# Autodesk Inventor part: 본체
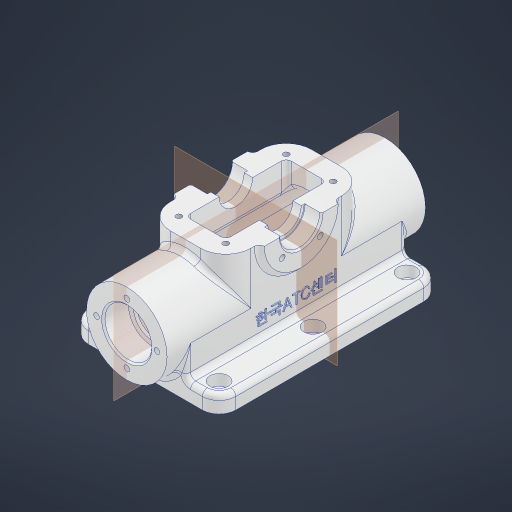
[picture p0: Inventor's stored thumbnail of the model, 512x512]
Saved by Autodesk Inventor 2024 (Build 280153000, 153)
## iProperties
Created: 2024-06
Part Number: 본체
Material: 알루미늄 6061
Document SubType Name: Modeling
Designer: kh_501
Density: 2.7 g/cm^3
Appearance: 알루미늄 - 평지
Mass: 550.949 g
Surface Area: 613.729 cm^2
Volume: 204.055 cm^3
Author: kh_501
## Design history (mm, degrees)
sketch "스케치1"
  geometry: L1 (-44, -66)-(44, -66); L2 (44, -66)-(44, 66); L3 (44, 66)-(-44, 66); L4 (-44, 66)-(-44, -66); L5 (-44, -66)-(44, 66); L6 (44, -66)-(-44, 66); 1 further point
  constraints: 12 end point, 2 midpoint, 2 parallel, 1 horizontal, 1 perpendicular
  dimensions: "d0" = 88 distance of L2.end L3.end; "d1" = 132 distance of L1.end L2.end
extrude "돌출1" new body sketch "스케치1" distance "d2" = 10; taper "d3" = 0 deg
sketch "스케치2"
  geometry: L1 (-44, 0)-(44, 0) reference; C1 r 24 at (0, 28); 2 further points
  constraints: 1 centre point, 1 midpoint, 1 vertical alignment
  dimensions: "d4" = 48 diameter of C1; "d5" = 28 distance from line of L1 C1.centre
extrude "돌출2" join sketch "스케치2" stored distance "d6" = 154; taper "d7" = 0 deg
node "작업 평면2"
sketch "스케치5"
  geometry: L1 (-44, -66)-(-15.875, -66) reference; L2 (15.875, -66)-(44, -66) reference; L3 (-44, 66)-(-44, -66) reference; L4 (-24, -77)-(24, -77) reference; L5 (24, 77)-(-24, 77) reference; L6 (15.875, -66)-(-15.875, -66) reference; L7 (15.875, 66)-(15.875, -66) reference; L8 (-15.875, 66)-(15.875, 66) reference; L9 (-15.875, -66)-(-15.875, 66) reference; L10 (24, 66)-(-24, 66); L11 (-24, 66)-(-24, -66); L12 (-24, -66)-(24, -66); L13 (24, -66)-(24, 66); L14 (24, 66)-(-24, -66); L15 (-24, 66)-(24, -66); 7 further points
  constraints: 12 end point, 2 midpoint, 2 parallel, 1 collinear, 1 horizontal, 1 perpendicular
  dimensions: "d13" = 48 distance of L11.end L12.end
extrude "돌출4" join sketch "스케치5" stored distance "d14" = 59; taper "d15" = 0 deg
sketch "스케치3"
  geometry: L1 (-24, -42)-(24, -42); L2 (24, -42)-(24, 42); L3 (24, 42)-(-24, 42); L4 (-24, 42)-(-24, -42); L5 (-24, -42)-(24, 42); L6 (24, -42)-(-24, 42); 1 further point
  constraints: 12 end point, 2 midpoint, 2 parallel, 1 horizontal, 1 perpendicular
  dimensions: "d9" = 84 distance of L1.end L2.end; "d10" = 48 distance of L2.end L3.end
extrude "돌출3" join sketch "스케치3" stored distance "d11" = 59; taper "d12" = 0 deg
sketch "스케치7"
  geometry: C1 r 24 at (0, 0) reference; 2 further points
  constraints: 1 coincident
hole "구멍1" sketch "스케치7" at (0, 0) diameter "d16" = 22; stored, may be unused: countersink angle "d20" = 90 deg, drill point angle "d22" = 118 deg; dims "d17" = 6, "d18" = 28, "d19" = 15, "d21" = 8
sketch "스케치8"
  geometry: C1 r 24 at (0, 0) reference; 2 further points
  constraints: 1 coincident
hole "구멍2" sketch "스케치8" at (0, 0) diameter "d23" = 22; stored, may be unused: countersink angle "d27" = 90 deg, drill point angle "d29" = 118 deg; dims "d24" = 6, "d25" = 28, "d26" = 15, "d28" = 8
sketch "스케치9"
  geometry: L1 (-18, 28)-(-18, 0); L2 (18, 28)-(18, 0); L3 (-24, 59)-(-24, 28) reference; L4 (-24, 10)-(-24, 28) reference; L5 (-18, 0)-(18, 0); C1 r 11 at (0, 28) reference; A1 r 18 centre (0, 28) between (-18, 28) and (18, 28); 1 further point
  constraints: 6 end point, 2 point on circle, 2 tangent, 2 vertical, 1 centre point, 1 coincident, 1 horizontal
  dimensions: "d30" = 6 distance between parallel lines of L4 L1
extrude "돌출5" cut sketch "스케치9" stored distance "d31" = 120; taper "d32" = 0 deg
sketch "스케치10"
  geometry: L1 (-24, 42)-(-24, -42) reference; L2 (-24, -42)-(24, -42) reference; L3 (24, -42)-(24, 42) reference; L4 (24, 42)-(-24, 42) reference; L5 (12, 30)-(-12, 30); L6 (-12, 30)-(-12, -30); L7 (-12, -30)-(12, -30); L8 (12, -30)-(12, 30); L9 (12, 30)-(-12, -30); L10 (-12, 30)-(12, -30); 1 further point
  constraints: 12 end point, 2 midpoint, 2 parallel, 1 horizontal, 1 perpendicular
  dimensions: "d33" = 60 distance of L5.end L6.end; "d34" = 24 distance of L5.start L5.end
extrude "돌출6" cut sketch "스케치10" stored distance "d35" = 120; taper "d36" = 0 deg
sketch "스케치11"
  geometry: L1 (24, 49)-(108, 49) reference; C1 r 22 at (66, 49); 3 further points
  constraints: 1 centre point, 1 midpoint
  dimensions: "d37" = 44 diameter of C1
extrude "돌출7" join sketch "스케치11" distance "d38" = 3; taper "d39" = 0 deg
sketch "스케치12"
  geometry: A1 r 22 centre (66, 49) between (44, 49) and (88, 49) reference; 2 further points
  constraints: 1 coincident
hole "구멍3" sketch "스케치12" at (66, 49) diameter "d40" = 20; stored, may be unused: countersink angle "d44" = 90 deg, drill point angle "d46" = 118 deg; dims "d41" = 6, "d42" = 24, "d43" = 10, "d45" = 8
sketch "스케치13"
  geometry: L1 (-17, -12)-(-27, -12) reference; L2 (-27, -12)-(-27, -22) reference; L3 (-24, -22)-(-27, -22) reference; L4 (-24, -22)-(-24, -42) reference; L5 (-24, -42)-(24, -42) reference; L6 (24, -42)-(24, -22) reference; L7 (24, -22)-(27, -22) reference; L8 (27, -12)-(27, -22) reference; L9 (27, -12)-(17, -12) reference; L10 (17, -12)-(17, -10) reference; L11 (17, -10)-(12, -10) reference; L12 (12, -10)-(12, -30) reference; L13 (12, -30)-(-12, -30) reference; L14 (-12, -30)-(-12, -10) reference; L15 (-12, -10)-(-17, -10) reference; L16 (-17, -10)-(-17, -12) reference; L17 (14, 32)-(-14, 32); L18 (-14, 32)-(-14, -32); L19 (-14, -32)-(14, -32); L20 (14, -32)-(14, 32); L21 (14, 32)-(-14, -32); L22 (-14, 32)-(14, -32); 5 further points
  constraints: 12 end point, 4 coincident, 2 midpoint, 2 parallel, 1 horizontal, 1 perpendicular
  dimensions: "d47" = 64 distance of L17.end L18.end; "d48" = 28 distance of L17.start L17.end
hole "구멍4" sketch "스케치13" at (-14, -32), (-14, 32), (14, -32), (14, 32) diameter "d49" = 3.45873; stored, may be unused: countersink angle "d53" = 90 deg, drill point angle "d55" = 118 deg; dims "d50" = 8, "d51" = 24, "d52" = 10, "d54" = 10
sketch "스케치14" dims "d56" = 36
  geometry: L1 (0, 0)-(0, 18); C1 r 24 at (0, 0) reference; 2 further points
  constraints: 2 coincident, 2 end point, 1 vertical, 1 vertical alignment, 2 other
hole "구멍5" sketch "스케치14" at (0, 18) diameter "d57" = 3.45873; stored, may be unused: countersink angle "d61" = 90 deg, drill point angle "d63" = 118 deg; dims "d58" = 8, "d59" = 4, "d60" = 2, "d62" = 10
sketch "스케치15"
  geometry: L1 (24, -66)-(44, -66) reference; L2 (-44, -66)-(-24, -66) reference; L3 (-24, -66)-(-24, 66) reference; L4 (-24, 66)-(-44, 66) reference; L5 (-44, 66)-(-44, -66) reference; L6 (-44, -66)-(-24, -66) reference; L7 (24, 66)-(24, -66) reference; L8 (24, -66)-(44, -66) reference; L9 (44, -66)-(44, 66) reference; L10 (44, 66)-(24, 66) reference; L11 (34, 56)-(-34, 56); L12 (-34, 56)-(-34, -56); L13 (-34, -56)-(34, -56); L14 (34, -56)-(34, 56); L15 (34, 56)-(-34, -56); L16 (-34, 56)-(34, -56); 7 further points
  constraints: 12 end point, 4 coincident, 4 midpoint, 2 parallel, 1 horizontal, 1 perpendicular
  dimensions: "d67" = 68 distance of L11.start L11.end; "d68" = 112 distance of L11.end L12.end
hole "구멍6" sketch "스케치15" at (34, -56), (34, 56), (-34, 56), (-34, -56), (34, 0), (-34, 0) diameter "d69" = 6.6; stored, may be unused: countersink angle "d73" = 90 deg, drill point angle "d75" = 118 deg; dims "d70" = 8, "d71" = 11, "d72" = 6.6, "d74" = 10
sketch "스케치16" dims "d76" = 32
  geometry: L1 (66, 49)-(66, 15.025); L2 (66, 49)-(35.317, 18.317); L3 (66, 49)-(96.683, 18.317); A1 r 22 centre (66, 49) between (44, 49) and (88, 49) reference; 3 further points
  constraints: 6 end point, 2 point on line, 2 symmetric about line, 1 coincident, 1 vertical, 3 other
  dimensions: "d77" = 45 deg angle of L1 L2
hole "구멍7" sketch "스케치16" at (54.686, 37.686), (77.314, 37.686) diameter "d78" = 3.45873; stored, may be unused: countersink angle "d82" = 90 deg, drill point angle "d84" = 118 deg; dims "d79" = 8, "d80" = 11, "d81" = 6.6, "d83" = 10.8
sketch "스케치17"
  geometry: L1 (0, -10)-(132, -10) reference; 3 further points
  constraints: 1 midpoint, 1 vertical alignment, 1 other
  dimensions: "d85" = 20 distance from line of L1 point (66, 10)
feature "엠보싱1" sketch "스케치17" dims "d86" = 0.5, "d87" = 0
fillet "모깎기1" dims "d88" = 15
fillet "모깎기2" dims "d89" = 10
fillet "모깎기3" dims "d90" = 3
fillet "모깎기4" dims "d91" = 3
fillet "모깎기9" dims "d96" = 3
fillet "모깎기10" dims "d97" = 3
fillet "모깎기11" dims "d98" = 3
chamfer "모따기1" distance "d99" = 1; stored, may be unused: second distance "d100" = 2, angle "d101" = 45 deg
fillet "모깎기12" dims "d102" = 3
fillet "모깎기13" dims "d103" = 0.3
chamfer "모따기2" distance "d104" = 1; stored, may be unused: second distance "d105" = 2, angle "d106" = 45 deg
fillet "모깎기14" dims "d107" = 3
node "작업축1"
node "작업 평면3"
node "작업 평면4"
fillet "모깎기5" dims "d92" = 3
fillet "모깎기7" dims "d94" = 3
fillet "모깎기8" dims "d95" = 3
fillet "모깎기6" dims "d93" = 3
feature "؝耀؟耀ء耀أ耀إ耀ا耀ة耀ث耀" dims "d0" = 88, "d1" = 132, "d2" = 10, "d3" = 0, "d4" = 48, "d5" = 28, "d6" = 154, "d7" = 0, "d8" = 59, "d9" = 84, "d10" = 48, "d11" = 59, "d12" = 0, "d13" = 48, "d14" = 59, "d15" = 0, "d16" = 22, "d17" = 6, "d18" = 28, "d19" = 15, "d20" = 90 deg, "d21" = 8, "d22" = 118 deg, "d23" = 22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
node "솔리드1"
mirror "미러1"
pattern_circular "원형 패턴1" dims angle "d65" = 360 deg
mirror "미러2"
mirror "미러3"
node "투영된 루프1"
node "투영된 루프2"
node "투영된 루프3"
node "투영된 루프4"
node "투영된 루프5"
feature "A9D066F2-1C7D-4E18-AEED-F7BC21143FA4" dims "d16" = 22, "d17" = 6, "d18" = 28, "d19" = 15, "d20" = 90 deg, "d21" = 8, "d22" = 118 deg
